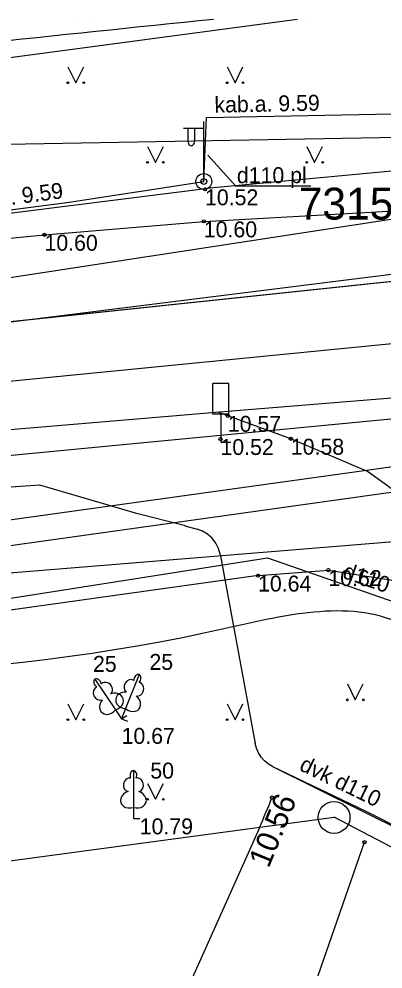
# Model space of a CAD drawing. Extents: x 502312.8 to 502402.4, y 308528.5 to 308602.
# Drawn here: x 502353.22 to 502364.65, y 308572.17 to 308602 of the extents above; entities that cross this region are included whole.
import ezdxf

# ---------------------------------------------------------------- set-up
doc = ezdxf.new("R2010")
doc.units = 0
for name, color, linetype in [('24', 7, 'Continuous'), ('38', 7, 'Continuous'), ('39', 7, 'Continuous'), ('APGR_ELEM_####_####_#', 7, 'Continuous'), ('APGR_SARK_####_####_#', 7, 'Continuous'), ('APGS_ACRL_####_####_#', 7, 'Continuous'), ('APGS_ACRL_####_TKST_#', 7, 'Continuous'), ('APGS_ELEM_####_####_#', 7, 'Continuous'), ('APGS_VADP_ZSPR_####_I', 7, 'Continuous'), ('APGS_VADP_ZSPR_TKST_I', 7, 'Continuous'), ('CELI_CAPM_####_####_#', 7, 'Continuous'), ('CELI_CMAL_####_####_#', 7, 'Continuous'), ('CELI_ELEM_####_####_#', 7, 'Continuous'), ('ELEK_ACRL_####_####_#', 7, 'Continuous'), ('ELEK_ACRL_####_TKST_#', 7, 'Continuous'), ('ELEK_VADP_ZSPR_####_#', 7, 'Continuous'), ('ELEK_VADV_ZSPR_####_#', 7, 'Continuous'), ('GAZE_VADP_VSP2_####_#', 7, 'Continuous'), ('Level 51-1', 7, 'Continuous'), ('RELJ_AATZ_####_TKST_#', 7, 'Continuous'), ('RELJ_ELEM_####_####_#', 7, 'Continuous'), ('SAKK_KKAN_####_####_#', 7, 'Continuous'), ('SKAN_VADP_PAST_####_I', 7, 'Continuous'), ('TERT_DIAM_####_TKST_#', 7, 'Continuous'), ('TERT_ELEM_####_####_#', 7, 'Continuous'), ('TERT_KONT_####_####_#', 7, 'Continuous'), ('UDTK_VADP_UDEN_####_#', 7, 'Continuous'), ('UDTK_VADP_UDEN_####_I', 7, 'Continuous'), ('UDTK_VADP_UDEN_TKST_#', 7, 'Continuous')]:
    doc.layers.add(name, color=color, linetype=linetype)

msp = doc.modelspace()

# ---------------------------------------------------------------- linework, layer by layer
at = {"layer": '24'}
for p, q in [((502351.582, 308592.356), (502382.507, 308595.627)), ((502343.246, 308583.821), (502364.984, 308585.593))]:
    msp.add_line(p, q, dxfattribs=at)
at = {"layer": '38'}
msp.add_lwpolyline([(502312.806, 308585.911), (502321.144, 308587.612), (502337.181, 308590.44), (502351.582, 308592.356), (502382.507, 308595.627), (502382.531, 308595.63), (502383.93, 308595.78), (502383.493, 308598.901), (502376.9, 308598.344), (502359.324, 308596.701), (502339.771, 308594.239), (502329.531, 308592.488), (502312.806, 308589.016)], dxfattribs=at)
at = {"layer": 'APGR_ELEM_####_####_#'}
msp.add_circle((502363.11, 308576.93), 0.5, dxfattribs=at)
at = {"layer": 'APGR_SARK_####_####_#'}
for p, q in [((502312.806, 308595.403), (502361.947, 308602.001)), ((502312.806, 308570.179), (502363.114, 308576.934)), ((502369.848, 308573.414), (502363.114, 308576.934))]:
    msp.add_line(p, q, dxfattribs=at)
at = {"layer": 'APGS_ACRL_####_####_#'}
for p, q in [((502359.02, 308596.899), (502359.099, 308598.905)), ((502345.961, 308595.098), (502354.788, 308596.247))]:
    msp.add_line(p, q, dxfattribs=at)
at = {"layer": 'APGS_ACRL_####_TKST_#'}
msp.add_lwpolyline([(502362.38, 308596.757), (502360.025, 308596.757), (502359.145, 308597.723)], dxfattribs=at)
at = {"layer": 'APGS_ELEM_####_####_#'}
for p, q in [((502359.02, 308598.566), (502358.385, 308598.561)), ((502358.52, 308598.562), (502358.52, 308598.17)), ((502358.73, 308598.564), (502358.73, 308598.17)), ((502359.02, 308596.899), (502359.02, 308598.782))]:
    msp.add_line(p, q, dxfattribs=at)
for radius in [0.25, 0.09]:
    msp.add_circle((502359.02, 308596.899), radius, dxfattribs=at)
msp.add_ellipse((502358.625, 308598.17), major_axis=(0, 0.151), ratio=0.695971, start_param=1.570796, end_param=4.712389, dxfattribs=at)
at = {"layer": 'APGS_VADP_ZSPR_####_I'}
for points in [[(502359.02, 308596.899), (502359.099, 308598.905), (502381.407, 308599.345), (502389.408, 308599.27)], [(502328.899, 308593.021), (502345.961, 308595.098), (502354.788, 308596.247), (502359.02, 308596.899)]]:
    msp.add_lwpolyline(points, dxfattribs=at)
at = {"layer": 'CELI_CAPM_####_####_#'}
for points in [[(502312.806, 308589.961), (502322.46, 308591.329), (502333.461, 308592.851), (502346.075, 308594.464), (502354.016, 308595.225), (502359.019, 308595.646), (502368.001, 308596.15), (502374.084, 308596.461), (502389.008, 308597.854), (502397.381, 308598.824), (502402.407, 308599.392)], [(502402.407, 308593.847), (502399.48, 308593.528), (502378.687, 308591.22), (502359.769, 308589.676), (502350.692, 308588.911), (502341.476, 308587.869), (502335.517, 308587.096)], [(502373.303, 308574.647), (502370.341, 308581.042), (502368.721, 308584.133), (502365.049, 308587.15), (502364.156, 308587.797), (502361.753, 308588.821), (502359.465, 308589.651)]]:
    msp.add_lwpolyline(points, dxfattribs=at)
at = {"layer": 'CELI_CMAL_####_####_#'}
for p, q in [((502360.723, 308584.523), (502362.932, 308584.696)), ((502360.772, 308576.607), (502357.743, 308569.847)), ((502361.131, 308567.739), (502364.065, 308576.152))]:
    msp.add_line(p, q, dxfattribs=at)
for points in [[(502365.049, 308587.15), (502341.875, 308583.905), (502332.578, 308582.643)], [(502360.723, 308584.523), (502342.387, 308581.96), (502332.395, 308580.6)], [(502362.932, 308584.696), (502365.084, 308584.364), (502366.368, 308583.65)]]:
    msp.add_lwpolyline(points, dxfattribs=at)
msp.add_arc((502112.61, 308679.677), 268.715, 337.44522, 337.66445, dxfattribs=at)
at = {"layer": 'CELI_ELEM_####_####_#'}
for p, q in [((502359.8, 308590.56), (502359.3, 308590.56)), ((502359.3, 308589.591), (502359.3, 308590.56)), ((502359.8, 308589.591), (502359.8, 308590.56)), ((502359.8, 308589.591), (502359.3, 308589.591)), ((502359.554, 308589.591), (502359.554, 308588.713)), ((502359.554, 308588.713), (502359.869, 308588.713))]:
    msp.add_line(p, q, dxfattribs=at)
at = {"layer": 'ELEK_ACRL_####_####_#'}
msp.add_line((502361.181, 308578.53), (502371.756, 308573.259), dxfattribs=at)
at = {"layer": 'ELEK_VADP_ZSPR_####_#'}
for p, q in [((502358.427, 308586.09), (502358.811, 308585.984)), ((502359.528, 308585.202), (502360.63, 308579.25)), ((502361.181, 308578.53), (502364.105, 308577.13)), ((502364.105, 308577.13), (502371.756, 308573.259))]:
    msp.add_line(p, q, dxfattribs=at)
for points in [[(502352.365, 308587.274), (502353.861, 308587.371), (502356.867, 308586.497), (502358.449, 308586.101)], [(502359.528, 308585.202), (502359.479, 308585.376), (502359.397, 308585.544), (502359.282, 308585.696), (502359.14, 308585.823), (502358.98, 308585.92), (502358.811, 308585.984)], [(502361.181, 308578.53), (502361.048, 308578.606), (502360.926, 308578.705), (502360.819, 308578.823), (502360.733, 308578.957), (502360.669, 308579.101), (502360.63, 308579.25)]]:
    msp.add_lwpolyline(points, dxfattribs=at)
at = {"layer": 'ELEK_VADV_ZSPR_####_#'}
for p, q in [((502352.204, 308588.229), (502386.138, 308591.478)), ((502352.427, 308586.209), (502386.227, 308590.894))]:
    msp.add_line(p, q, dxfattribs=at)
at = {"layer": 'GAZE_VADP_VSP2_####_#'}
msp.add_lwpolyline([(502345.988, 308589.948), (502370.881, 308592.394), (502385.772, 308593.858)], dxfattribs=at)
at = {"layer": 'Level 51-1'}
msp.add_line((502343.246, 308583.821), (502364.984, 308585.593), dxfattribs=at)
at = {"layer": 'RELJ_ELEM_####_####_#'}
for centre in [(502359.057, 308596.652), (502359.019, 308595.646), (502354.016, 308595.225), (502359.774, 308589.539), (502359.543, 308588.812), (502361.753, 308588.821), (502360.723, 308584.523), (502362.932, 308584.696), (502361.164, 308577.557), (502364.065, 308576.152)]:
    msp.add_circle(centre, 0.05, dxfattribs=at)
at = {"layer": 'SAKK_KKAN_####_####_#'}
msp.add_lwpolyline([(502345.861, 308593.28), (502351.83, 308593.722), (502374.471, 308597.177)], dxfattribs=at)
at = {"layer": 'SKAN_VADP_PAST_####_I'}
msp.add_line((502339.455, 308590.813), (502369.581, 308594.569), dxfattribs=at)
at = {"layer": 'TERT_ELEM_####_####_#'}
for p, q in [((502355, 308602), (502355, 308602.001)), ((502355.4, 308602), (502355.4, 308602.001)), ((502362, 308602), (502362, 308602.001)), ((502362.4, 308602), (502362.4, 308602.001)), ((502354.75, 308600.5), (502355, 308600)), ((502355, 308600), (502355.25, 308600.5)), ((502359.75, 308600.5), (502360, 308600)), ((502360, 308600), (502360.25, 308600.5)), ((502357.25, 308598), (502357.5, 308597.5)), ((502357.5, 308597.5), (502357.75, 308598)), ((502362.25, 308598), (502362.5, 308597.5)), ((502362.5, 308597.5), (502362.75, 308598)), ((502363.527, 308581.124), (502363.777, 308580.624)), ((502363.777, 308580.624), (502364.027, 308581.124)), ((502354.75, 308580.5), (502355, 308580)), ((502355, 308580), (502355.25, 308580.5)), ((502356.565, 308580.346), (502356.437, 308580.023)), ((502359.75, 308580.5), (502360, 308580)), ((502360, 308580), (502360.25, 308580.5)), ((502356.243, 308580.311), (502356.437, 308580.023)), ((502356.437, 308580.023), (502356.603, 308580.135)), ((502356.437, 308580.023), (502356.623, 308579.949)), ((502357.25, 308578), (502357.5, 308577.5)), ((502357.5, 308577.5), (502357.75, 308578)), ((502356.808, 308577.247), (502356.808, 308576.9)), ((502356.808, 308576.9), (502357.008, 308576.9))]:
    msp.add_line(p, q, dxfattribs=at)
for points in [[(502355.598, 308581.267), (502356.243, 308580.311)], [(502356.988, 308581.418), (502356.565, 308580.346)], [(502355.802, 308581.124), (502355.801, 308581.124)], [(502356.986, 308581.169), (502356.986, 308581.17)], [(502356.808, 308578.4), (502356.808, 308577.247)], [(502356.898, 308578.168), (502356.897, 308578.169)]]:
    msp.add_lwpolyline(points, dxfattribs=at)
for centre, radius in [((502354.75, 308600), 0.028), ((502355.25, 308600), 0.0263), ((502359.75, 308600), 0.028), ((502360.25, 308600), 0.0263), ((502357.25, 308597.5), 0.028), ((502357.75, 308597.5), 0.0263), ((502362.25, 308597.5), 0.028), ((502362.75, 308597.5), 0.0263), ((502363.527, 308580.623), 0.028), ((502364.027, 308580.623), 0.0263), ((502354.75, 308580), 0.028), ((502355.25, 308580), 0.0263), ((502359.75, 308580), 0.028), ((502360.25, 308580), 0.0263), ((502357.25, 308577.5), 0.028), ((502357.75, 308577.5), 0.0263)]:
    msp.add_circle(centre, radius, dxfattribs=at)
for centre, major_axis, ratio, start_param, end_param in [((502355.682, 308581.143), (0.084, -0.124), 0.707107, 3.14537, 5.287485), ((502355.682, 308581.142), (0.084, -0.124), 0.707107, 0.995701, 3.137816), ((502356.706, 308581.051), (-0.114, -0.183), 0.861323, 3.141593, 6.283185), ((502356.934, 308581.278), (-0.055, -0.139), 0.707107, 3.14537, 5.287485), ((502356.933, 308581.279), (-0.055, -0.139), 0.707107, 0.995701, 3.137816), ((502355.741, 308580.826), (0.087, -0.198), 0.861323, 3.141593, 6.283185), ((502355.953, 308580.97), (0.151, -0.154), 0.861323, 0, 3.141593), ((502356.944, 308580.957), (-0.042, -0.212), 0.861323, 0, 3.141593), ((502356.031, 308580.464), (0.201, 0.25), 0.814445, 1.570796, 4.752015), ((502356.18, 308580.565), (-0.308, -0.093), 0.814445, 1.531171, 4.712389), ((502356.572, 308580.607), (0.32, -0.024), 0.814445, 1.570796, 4.752015), ((502356.738, 308580.541), (-0.25, 0.201), 0.814445, 1.531171, 4.712389), ((502356.808, 308578.25), (0, -0.15), 0.707107, 3.14537, 5.287485), ((502356.808, 308578.25), (0, -0.15), 0.707107, 0.995701, 3.137816), ((502356.68, 308577.955), (-0.039, -0.212), 0.861323, 3.141593, 6.283185), ((502356.936, 308577.955), (0.039, -0.212), 0.861323, 0, 3.141593), ((502356.718, 308577.493), (0.307, 0.095), 0.814445, 1.570796, 4.752015), ((502356.898, 308577.493), (-0.307, 0.095), 0.814445, 1.531171, 4.712389)]:
    msp.add_ellipse(centre, major_axis=major_axis, ratio=ratio, start_param=start_param, end_param=end_param, dxfattribs=at)
at = {"layer": 'TERT_KONT_####_####_#'}
for points in [[(502312.806, 308596.715), (502320.791, 308597.881), (502332.656, 308599.172), (502344.523, 308600.445), (502359.328, 308602.001)], [(502368.421, 308580.073), (502364.888, 308583.145), (502359.074, 308582.726), (502336.999, 308579.84), (502335.385, 308579.318), (502336.097, 308569.387), (502336.741, 308557.487), (502335.314, 308546.766)]]:
    msp.add_spline(points, degree=3, dxfattribs=at)
at = {"layer": 'UDTK_VADP_UDEN_####_#'}
msp.add_lwpolyline([(502350.697, 308580.556), (502351.744, 308583.627), (502361.023, 308585.084), (502372.36, 308581.134), (502374.586, 308576.669)], dxfattribs=at)
at = {"layer": 'UDTK_VADP_UDEN_####_I'}
msp.add_lwpolyline([(502324.63, 308594.872), (502351.064, 308598.035), (502366.307, 308598.312), (502381.551, 308598.59), (502384.121, 308597.913)], dxfattribs=at)

# ---------------------------------------------------------------- texts
at = {"layer": '39'}
msp.add_text('7315030100008', height=1, dxfattribs=at).set_placement((502361.999, 308595.704))
at = {"layer": 'APGS_ACRL_####_TKST_#'}
msp.add_text('d110 pl', height=0.5, dxfattribs=at).set_placement((502360.058, 308596.846))
msp.add_text('c.a. 9.59', height=0.5, rotation=7.4164, dxfattribs=at).set_placement((502352.082, 308596.046))
at = {"layer": 'APGS_VADP_ZSPR_TKST_I'}
msp.add_text('kab.a. 9.59', height=0.5, rotation=1.1299, dxfattribs=at).set_placement((502359.357, 308599.06))
at = {"layer": 'ELEK_ACRL_####_TKST_#'}
msp.add_text('dvk d110', height=0.5, rotation=334.0377, dxfattribs=at).set_placement((502361.986, 308578.431))
at = {"layer": 'RELJ_AATZ_####_TKST_#'}
for s, p in [('10.52', (502359.057, 308596.152)), ('10.60', (502359.019, 308595.146)), ('10.60', (502354.016, 308594.725)), ('10.57', (502359.774, 308589.039)), ('10.52', (502359.543, 308588.312)), ('10.58', (502361.753, 308588.321)), ('10.64', (502360.723, 308584.023)), ('10.62', (502362.932, 308584.196)), ('10.67', (502356.438, 308579.24)), ('10.79', (502357.008, 308576.4))]:
    msp.add_text(s, height=0.5, dxfattribs=at).set_placement(p)
msp.add_text('10.56', height=0.7, rotation=67.6551, dxfattribs=at).set_placement((502361.055, 308575.314))
at = {"layer": 'TERT_DIAM_####_TKST_#'}
for s, p in [('25', (502355.539, 308581.502)), ('25', (502357.312, 308581.563)), ('50', (502357.34, 308578.15))]:
    msp.add_text(s, height=0.5, dxfattribs=at).set_placement(p)
at = {"layer": 'UDTK_VADP_UDEN_TKST_#'}
msp.add_text('d110', height=0.5, rotation=340.7908, dxfattribs=at).set_placement((502363.348, 308584.461))

doc.saveas('drawing.dxf')
